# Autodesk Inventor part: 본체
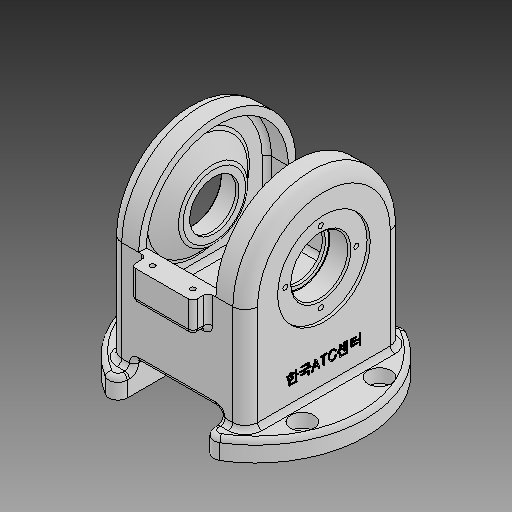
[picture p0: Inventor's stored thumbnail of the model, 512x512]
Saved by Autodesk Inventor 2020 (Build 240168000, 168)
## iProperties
Created: 2025-02
Part Number: 본체
Material: 일반
Document SubType Name: Modeling
Designer: 1강의실14
Density: 1 g/cm^3
Appearance: 기본값
Author: jhkim
Sending System: Autodesk Inventor 2025
Preprocessor: ST-DEVELOPER v20
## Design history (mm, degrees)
feature "솔리드2"
node "솔리드1"
